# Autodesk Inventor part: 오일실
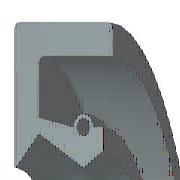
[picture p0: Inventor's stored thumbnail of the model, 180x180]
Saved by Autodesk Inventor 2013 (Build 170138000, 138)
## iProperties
Created: 2014-07
Part Number: 오일실
Material: 고무
Description: 오일-실
Document SubType Name: Modeling
Standard: KS B 2804
Designer: KYOUNG IL JANG
Standards Organization: KS
Language: ko-KR
Size Designation: D - 10 20 7
Categories: <MemberInstance><Categories><Category DisplayName="샤프트 부품" InternalName="7f7aeb1f-a693-4053-b835-cee3144e0d98" Mnemonic="SHFT"><Category DisplayName="실링" Intern
Density: 0.93 g/cm^3
Company: 한국ATC센터
IsCustomPart: 0
Author: KYOUNG IL JANG
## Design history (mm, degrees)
revolve "본체" stored, may be unused: angle "d17" = 90 deg
revolve "스프링1" stored, may be unused: angle "d18" = 90 deg
body "Solid1"
sketch "스케치1"
  geometry: L1 (0, 10)-(7, 10); L2 (7, 8.25)-(1.75, 8.25); L3 (1.75, 6.75)-(4.9, 5); L4 (4.9, 5)-(0, 5); L5 (0, 0)-(9.586, 0) reference; L6 (4.9, 5)-(6.3, 5.875); L7 (0, 18)-(0, -3) reference; L8 (-1.941, 0)-(11.507, 0) reference; L9 (4.2, 7.1)-(1.75, 7.59); L10 (1.75, 7.59)-(1.75, 8.25); L11 (0, 10)-(0, 5.088); L12 (4.9, 5)-(0, 5); L13 (1.75, 6.75)-(0.152, 5.028); L14 (7, 10)-(7, 8.25); L15 (5.6, 7.1)-(6.3, 7.1); L16 (6.3, 7.1)-(6.3, 5.875); C1 r 0.455 at (4.9, 7.1); A1 r 0.7 centre (4.9, 7.1) between (5.6, 7.1) and (4.2, 7.1); A2 r 0.088 centre (0.088, 5.088) between (0, 5.088) and (0.152, 5.028); 1 further point
  constraints: 28 end point, 5 horizontal alignment, 5 point on line, 4 point on circle, 4 vertical alignment, 3 centre point, 3 tangent, 2 collinear, 2 horizontal, 2 perpendicular, 1 coincident, 1 parallel
  dimensions: "d0" = 20 diameter of L1 L5 (= SD2); "d1" = 1.75 distance of L1.end L2.start (= SD); "d2" = 0.91 diameter of C1 (= SPDI); "d3" = 1.4 diameter of A1 (= SPDA); "d4" = 10 diameter of L3.end L5 (= NND); "d5" = 13.5 diameter of L3.start L5 (= TKDM); "d7" = 15.18 diameter of L9.end L5 (= TKDM + 0.24 x SWDT); "d8" = 1.75 distance between parallel lines of L11 L10 (= SD); "d9" = 4.9 distance from line of L11 C1.centre (= SPDST); "d10" = 14.2 diameter of C1.centre L5 (= HLDM); "d11" = 0.0875 radius of A2 (= 0.25 x LAB); "d12" = 6.3 distance between parallel lines of L11 L16 (= SDI); "d13" = 11.75 diameter of L6.end L5 (= ABDM); "d14" = 7 distance from line of L11 L1.end (= SWDT)
fillet "모깎기1" dims "d6" = 0.3 (= RR)
other parameters: "SD2" = 20 [user parameter; used in 1 equation term], "SWDT" = 7 [user parameter; used in 2 equation terms], "RR" = 0.3 [user parameter; used in 1 equation term], "SD" = 1.75 [user parameter; used in 2 equation terms], "NND" = 10 [user parameter; used in 1 equation term], "SPDA" = 1.4 [user parameter; used in 1 equation term], "SPDI" = 0.91 [user parameter; used in 1 equation term], "TKDM" = 13.5 [user parameter; used in 2 equation terms], "HLDM" = 14.2 [user parameter; used in 1 equation term], "ABDM" = 11.75 [user parameter; used in 1 equation term], "SDI" = 6.3 [user parameter; used in 1 equation term], "SPDST" = 4.9 [user parameter; used in 1 equation term], "LAB" = 0.35 [user parameter; used in 1 equation term], "d15" = 0, "d16" = 0, "d19" = 0
